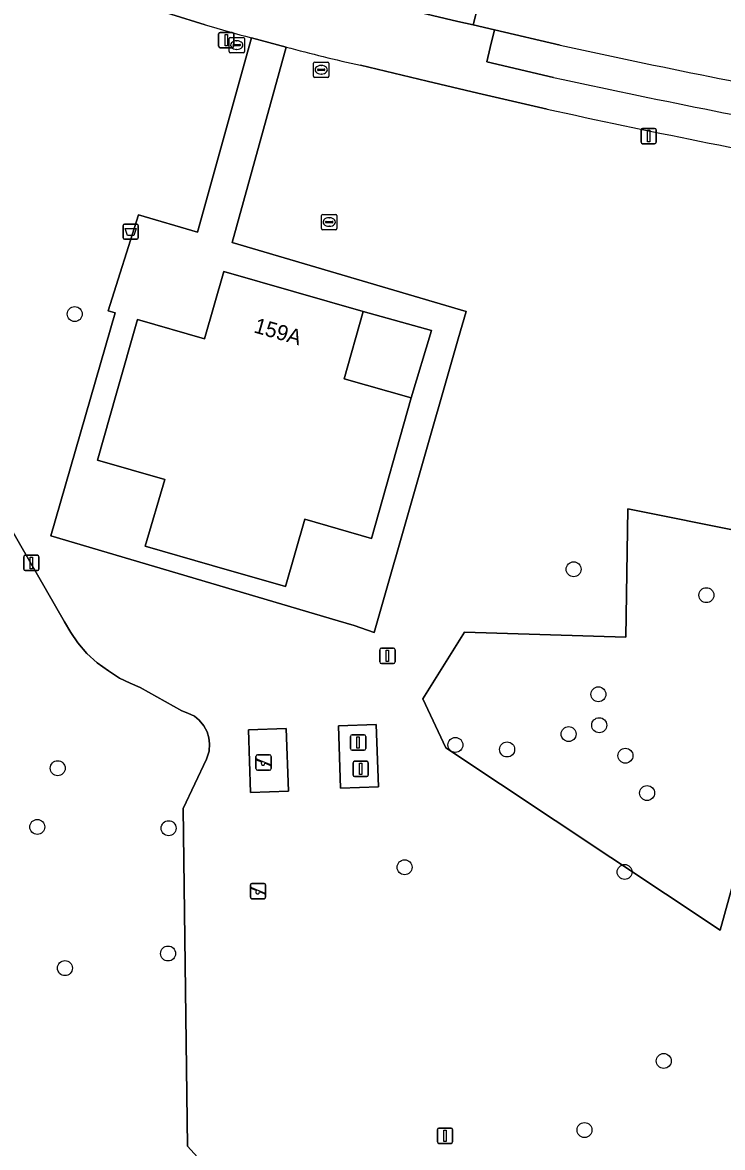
# Model space of a CAD drawing. Extents: x 161258 to 161838, y 380833 to 381727.
# Drawn here: x 161379.4 to 161425.2, y 381594 to 381667.5 of the extents above; entities that cross this region are included whole.
import ezdxf

# ---------------------------------------------------------------- set-up
doc = ezdxf.new("R2010")
doc.units = 0
for name, color, linetype in [('IMGEO_Afsluitpaal', 7, 'Continuous'), ('IMGEO_Afvalbak', 7, 'Continuous'), ('IMGEO_Boom', 7, 'Continuous'), ('IMGEO_Gemengd_bos', 7, 'Continuous'), ('IMGEO_Groenvoorziening', 7, 'Continuous'), ('IMGEO_Kolk', 7, 'Continuous'), ('IMGEO_Lichtmast', 7, 'Continuous'), ('IMGEO_Pand', 7, 'Continuous'), ('IMGEO_Pand_nummerreeks', 7, 'Continuous'), ('IMGEO_Parkeervlak_halfverhard', 7, 'Continuous'), ('IMGEO_Rijbaan_lokaal_open', 7, 'Continuous'), ('IMGEO_Rioolput', 7, 'Continuous'), ('IMGEO_Speelvoorziening', 7, 'Continuous'), ('IMGEO_Terreindeel_open', 7, 'Continuous'), ('IMGEO_Vlaggenmast', 7, 'Continuous'), ('IMGEO_Voetpad_open', 7, 'Continuous')]:
    doc.layers.add(name, color=color, linetype=linetype)

msp = doc.modelspace()

# ---------------------------------------------------------------- linework, layer by layer
at = {"layer": 'IMGEO_Afsluitpaal'}
for p, q in [((161400.856, 381620.042), (161400.856, 381620.842)), ((161400.856, 381620.842), (161400.856, 381620.042)), ((161400.956, 381620.942), (161401.746, 381620.942)), ((161401.746, 381620.942), (161400.956, 381620.942)), ((161401.846, 381620.842), (161401.846, 381620.042)), ((161401.846, 381620.042), (161401.846, 381620.842)), ((161401.746, 381619.942), (161400.956, 381619.942)), ((161400.956, 381619.942), (161401.746, 381619.942)), ((161401.023, 381618.318), (161401.023, 381619.118)), ((161401.023, 381619.118), (161401.023, 381618.318)), ((161401.123, 381619.218), (161401.913, 381619.218)), ((161401.913, 381619.218), (161401.123, 381619.218)), ((161402.013, 381619.118), (161402.013, 381618.318)), ((161402.013, 381618.318), (161402.013, 381619.118)), ((161401.913, 381618.218), (161401.123, 381618.218)), ((161401.123, 381618.218), (161401.913, 381618.218))]:
    msp.add_line(p, q, dxfattribs=at)
for points in [[(161401.276, 381620.817), (161401.426, 381620.817), (161401.426, 381620.067), (161401.276, 381620.067), (161401.276, 381620.817)], [(161401.443, 381619.093), (161401.593, 381619.093), (161401.593, 381618.343), (161401.443, 381618.343), (161401.443, 381619.093)]]:
    msp.add_lwpolyline(points, dxfattribs=at)
for centre, start, end in [((161400.956, 381620.842), 90, 180), ((161400.956, 381620.842), 90, 180), ((161401.746, 381620.842), 0, 90), ((161401.746, 381620.842), 360, 90), ((161400.956, 381620.042), 180, 270), ((161400.956, 381620.042), 180, 270), ((161401.746, 381620.042), 270, 0), ((161401.746, 381620.042), 270, 0), ((161401.123, 381619.118), 90, 180), ((161401.123, 381619.118), 90, 180), ((161401.913, 381619.118), 0, 90), ((161401.913, 381619.118), 360, 90), ((161401.123, 381618.318), 180, 270), ((161401.123, 381618.318), 180, 270), ((161401.913, 381618.318), 270, 0), ((161401.913, 381618.318), 270, 0)]:
    msp.add_arc(centre, 0.1, start, end, dxfattribs=at)
at = {"layer": 'IMGEO_Afvalbak'}
for p, q in [((161386.1, 381654.321), (161386.89, 381654.321)), ((161386.89, 381654.321), (161386.1, 381654.321)), ((161386, 381653.421), (161386, 381654.221)), ((161386, 381654.221), (161386, 381653.421)), ((161386.99, 381654.221), (161386.99, 381653.421)), ((161386.99, 381653.421), (161386.99, 381654.221)), ((161386.89, 381653.321), (161386.1, 381653.321)), ((161386.1, 381653.321), (161386.89, 381653.321))]:
    msp.add_line(p, q, dxfattribs=at)
msp.add_lwpolyline([(161386.143, 381654.035), (161386.847, 381654.035), (161386.698, 381653.565), (161386.292, 381653.565), (161386.143, 381654.035)], dxfattribs=at)
for centre, start, end in [((161386.1, 381654.221), 90, 180), ((161386.1, 381654.221), 90, 180), ((161386.89, 381654.221), 0, 90), ((161386.89, 381654.221), 360, 90), ((161386.1, 381653.421), 180, 270), ((161386.1, 381653.421), 180, 270), ((161386.89, 381653.421), 270, 0), ((161386.89, 381653.421), 270, 0)]:
    msp.add_arc(centre, 0.1, start, end, dxfattribs=at)
at = {"layer": 'IMGEO_Boom'}
for centre in [(161382.846, 381648.438), (161415.429, 381631.761), (161424.097, 381630.07), (161417.047, 381623.592), (161417.098, 381621.573), (161415.103, 381620.993), (161407.705, 381620.285), (161411.085, 381619.988), (161418.812, 381619.583), (161381.732, 381618.765), (161420.227, 381617.142), (161380.399, 381614.928), (161388.976, 381614.844), (161404.387, 381612.292), (161418.761, 381611.984), (161388.942, 381606.656), (161382.205, 381605.701), (161421.315, 381599.635), (161416.138, 381595.122)]:
    msp.add_circle(centre, 0.489, dxfattribs=at)
at = {"layer": 'IMGEO_Gemengd_bos'}
for points in [[(161392.773, 381591.226), (161390.219, 381594.066), (161389.922, 381616.123), (161391.46, 381619.355), (161391.634, 381619.875), (161391.656, 381620.356), (161391.605, 381620.751), (161391.491, 381621.146), (161391.275, 381621.526), (161390.981, 381621.893), (161390.658, 381622.158), (161390.242, 381622.367), (161389.838, 381622.503), (161387.123, 381624.033), (161386.473, 381624.327), (161385.77, 381624.643), (161385.052, 381625.131), (161384.32, 381625.648), (161383.645, 381626.251), (161383.057, 381626.955), (161382.583, 381627.63), (161382.181, 381628.334), (161376.186, 381638.709)], [(161426.68, 381634.173), (161418.967, 381635.706), (161418.846, 381627.333), (161408.294, 381627.656), (161405.585, 381623.296), (161407.091, 381620.098), (161424.991, 381608.183), (161426.307, 381612.909)]]:
    msp.add_lwpolyline(points, dxfattribs=at)
at = {"layer": 'IMGEO_Groenvoorziening'}
for points in [[(161391.37, 381667.33), (161386.886, 381668.72), (161334.877, 381686.353), (161332.875, 381684.207), (161332.497, 381684.358), (161308.899, 381657.34), (161323.248, 381645.463), (161342.599, 381633.765), (161351.063, 381627.808), (161358.392, 381621.525), (161365.093, 381614.244), (161367.696, 381609.218), (161369.804, 381602.566), (161370.364, 381589.068), (161368.045, 381579.46), (161365.828, 381572.142), (161359.235, 381542.5), (161358.088, 381525.588)], [(161381.277, 381633.951), (161385.48, 381648.52), (161385.02, 381648.657), (161387, 381654.92), (161390.867, 381653.781), (161394.382, 381666.485)], [(161396.659, 381665.882), (161393.126, 381653.115), (161408.406, 381648.613), (161407.893, 381646.823), (161402.4, 381627.633), (161401.084, 381628.097), (161400.041, 381628.391), (161381.277, 381633.951)], [(161413.689, 381661.83), (161409.167, 381662.867), (161405.857, 381663.645), (161401.512, 381664.693)], [(161376.186, 381638.709), (161382.181, 381628.334), (161382.583, 381627.63), (161383.057, 381626.955), (161383.645, 381626.251), (161384.32, 381625.648), (161385.052, 381625.131), (161385.77, 381624.643), (161386.473, 381624.327), (161387.123, 381624.033), (161389.838, 381622.503), (161390.242, 381622.367), (161390.658, 381622.158), (161390.981, 381621.893), (161391.275, 381621.526), (161391.491, 381621.146), (161391.605, 381620.751), (161391.656, 381620.356), (161391.634, 381619.875), (161391.46, 381619.355), (161389.922, 381616.123), (161390.219, 381594.066), (161392.773, 381591.226)], [(161451.968, 381587.039), (161454.812, 381586.172), (161454.469, 381587.787), (161449.116, 381608.641), (161435.423, 381611.203), (161433.603, 381611.544), (161428.272, 381612.541), (161426.307, 381612.909), (161424.991, 381608.183), (161407.091, 381620.098), (161405.585, 381623.296), (161408.294, 381627.656), (161418.846, 381627.333), (161418.967, 381635.706), (161426.68, 381634.173), (161443.415, 381630.846), (161443.337, 381631.151)]]:
    msp.add_lwpolyline(points, dxfattribs=at)
for points in [[(161396.654, 381621.359), (161396.798, 381617.269), (161394.33, 381617.182), (161394.185, 381621.271)], [(161402.53, 381621.627), (161402.675, 381617.537), (161400.206, 381617.45), (161400.062, 381621.539)]]:
    msp.add_lwpolyline(points, close=True, dxfattribs=at)
for centre, radius, start, end in [((161433.329, 381811.102), 149.77, 253.73044, 254.92722), ((161423.506, 381764.962), 102.653, 254.83898, 257.62808), ((161532.028, 382200.983), 551.988, 257.62047, 259.73428)]:
    msp.add_arc(centre, radius, start, end, dxfattribs=at)
at = {"layer": 'IMGEO_Kolk'}
for p, q in [((161392.928, 381665.587), (161392.928, 381666.439)), ((161393.003, 381666.513), (161393.855, 381666.513)), ((161393.187, 381666.007), (161393.187, 381666.019)), ((161393.23, 381666.056), (161393.628, 381666.056)), ((161393.416, 381666.293), (161393.441, 381666.293)), ((161393.671, 381666.019), (161393.671, 381666.007)), ((161393.929, 381666.439), (161393.929, 381665.587)), ((161393.855, 381665.513), (161393.003, 381665.513)), ((161393.625, 381665.97), (161393.227, 381665.97)), ((161393.439, 381665.733), (161393.414, 381665.733)), ((161398.443, 381663.974), (161398.443, 381664.826)), ((161398.518, 381664.9), (161399.37, 381664.9)), ((161398.931, 381664.68), (161398.956, 381664.68)), ((161399.444, 381664.826), (161399.444, 381663.974)), ((161399.37, 381663.9), (161398.518, 381663.9)), ((161398.702, 381664.394), (161398.702, 381664.406)), ((161399.14, 381664.357), (161398.742, 381664.357)), ((161398.745, 381664.443), (161399.143, 381664.443)), ((161398.954, 381664.12), (161398.929, 381664.12)), ((161399.186, 381664.406), (161399.186, 381664.394))]:
    msp.add_line(p, q, dxfattribs=at)
for points in [[(161392.928, 381665.587), (161392.928, 381666.439)], [(161393.003, 381666.513), (161393.855, 381666.513)], [(161393.929, 381666.439), (161393.929, 381665.587)], [(161393.855, 381665.513), (161393.003, 381665.513)], [(161398.443, 381663.974), (161398.443, 381664.826)], [(161398.518, 381664.9), (161399.37, 381664.9)], [(161399.444, 381664.826), (161399.444, 381663.974)], [(161399.37, 381663.9), (161398.518, 381663.9)]]:
    msp.add_lwpolyline(points, dxfattribs=at)
for centre, radius, start, end in [((161393.005, 381666.437), 0.0765, 91.55205, 178.44795), ((161393.005, 381666.437), 0.0765, 91.55205, 178.44795), ((161393.227, 381666.016), 0.0403, 85.87752, 175.75265), ((161393.224, 381666.006), 0.0366, 178.93798, 274.71019), ((161393.628, 381666.013), 0.043, 264.86636, 352.45326), ((161393.632, 381666.018), 0.0386, 1.73085, 96.63898), ((161393.853, 381666.437), 0.0765, 1.55205, 88.44795), ((161393.853, 381666.437), 0.0765, 1.55205, 88.44795), ((161393.005, 381665.589), 0.0765, 181.55205, 268.44795), ((161393.005, 381665.589), 0.0765, 181.55205, 268.44795), ((161393.853, 381665.589), 0.0765, 271.55205, 358.44795), ((161393.853, 381665.589), 0.0765, 271.55205, 358.44795), ((161398.52, 381664.824), 0.0765, 91.55205, 178.44795), ((161398.52, 381664.824), 0.0765, 91.55205, 178.44795), ((161399.368, 381664.824), 0.0765, 1.55205, 88.44795), ((161399.368, 381664.824), 0.0765, 1.55205, 88.44795), ((161398.52, 381663.976), 0.0765, 181.55205, 268.44795), ((161398.52, 381663.976), 0.0765, 181.55205, 268.44795), ((161398.742, 381664.403), 0.0403, 85.87752, 175.75265), ((161398.739, 381664.393), 0.0366, 178.93798, 274.71019), ((161399.143, 381664.4), 0.043, 264.86636, 352.45326), ((161399.147, 381664.405), 0.0386, 1.73085, 96.63898), ((161399.368, 381663.976), 0.0765, 271.55205, 358.44795), ((161399.368, 381663.976), 0.0765, 271.55205, 358.44795)]:
    msp.add_arc(centre, radius, start, end, dxfattribs=at)
for centre, major_axis, ratio, start_param, end_param in [((161393.415, 381666.013), (-0.387, 0.002), 0.722429, 4.712389, 7.853982), ((161393.44, 381666.013), (-0.39, 0.002), 0.717154, 1.570796, 4.712389), ((161398.93, 381664.4), (-0.387, 0.002), 0.722429, 4.712389, 7.853982), ((161398.955, 381664.4), (-0.39, 0.002), 0.717154, 1.570796, 4.712389)]:
    msp.add_ellipse(centre, major_axis=major_axis, ratio=ratio, start_param=start_param, end_param=end_param, dxfattribs=at)
at = {"layer": 'IMGEO_Lichtmast'}
for p, q in [((161392.241, 381665.938), (161392.241, 381666.738)), ((161392.241, 381666.738), (161392.241, 381665.938)), ((161392.341, 381666.838), (161393.131, 381666.838)), ((161393.131, 381666.838), (161392.341, 381666.838)), ((161393.231, 381666.738), (161393.231, 381665.938)), ((161393.231, 381665.938), (161393.231, 381666.738)), ((161393.131, 381665.838), (161392.341, 381665.838)), ((161392.341, 381665.838), (161393.131, 381665.838)), ((161419.83, 381659.668), (161419.83, 381660.468)), ((161419.83, 381660.468), (161419.83, 381659.668)), ((161419.93, 381660.568), (161420.72, 381660.568)), ((161420.72, 381660.568), (161419.93, 381660.568)), ((161420.82, 381660.468), (161420.82, 381659.668)), ((161420.82, 381659.668), (161420.82, 381660.468)), ((161420.72, 381659.568), (161419.93, 381659.568)), ((161419.93, 381659.568), (161420.72, 381659.568)), ((161379.514, 381631.774), (161379.514, 381632.574)), ((161379.514, 381632.574), (161379.514, 381631.774)), ((161379.614, 381632.674), (161380.404, 381632.674)), ((161380.404, 381632.674), (161379.614, 381632.674)), ((161380.504, 381632.574), (161380.504, 381631.774)), ((161380.504, 381631.774), (161380.504, 381632.574)), ((161380.404, 381631.674), (161379.614, 381631.674)), ((161379.614, 381631.674), (161380.404, 381631.674)), ((161402.774, 381625.708), (161402.774, 381626.508)), ((161402.774, 381626.508), (161402.774, 381625.708)), ((161402.874, 381626.608), (161403.664, 381626.608)), ((161403.664, 381626.608), (161402.874, 381626.608)), ((161403.764, 381626.508), (161403.764, 381625.708)), ((161403.764, 381625.708), (161403.764, 381626.508)), ((161403.664, 381625.608), (161402.874, 381625.608)), ((161402.874, 381625.608), (161403.664, 381625.608))]:
    msp.add_line(p, q, dxfattribs=at)
for points in [[(161392.661, 381666.713), (161392.811, 381666.713), (161392.811, 381665.963), (161392.661, 381665.963), (161392.661, 381666.713)], [(161420.25, 381660.443), (161420.4, 381660.443), (161420.4, 381659.693), (161420.25, 381659.693), (161420.25, 381660.443)], [(161379.934, 381632.549), (161380.084, 381632.549), (161380.084, 381631.799), (161379.934, 381631.799), (161379.934, 381632.549)], [(161403.194, 381626.483), (161403.344, 381626.483), (161403.344, 381625.733), (161403.194, 381625.733), (161403.194, 381626.483)]]:
    msp.add_lwpolyline(points, dxfattribs=at)
for centre, start, end in [((161392.341, 381666.738), 90, 180), ((161392.341, 381666.738), 90, 180), ((161393.131, 381666.738), 0, 90), ((161393.131, 381666.738), 360, 90), ((161392.341, 381665.938), 180, 270), ((161392.341, 381665.938), 180, 270), ((161393.131, 381665.938), 270, 0), ((161393.131, 381665.938), 270, 0), ((161419.93, 381660.468), 90, 180), ((161419.93, 381660.468), 90, 180), ((161420.72, 381660.468), 0, 90), ((161420.72, 381660.468), 360, 90), ((161419.93, 381659.668), 180, 270), ((161419.93, 381659.668), 180, 270), ((161420.72, 381659.668), 270, 0), ((161420.72, 381659.668), 270, 0), ((161379.614, 381632.574), 90, 180), ((161379.614, 381632.574), 90, 180), ((161380.404, 381632.574), 0, 90), ((161380.404, 381632.574), 360, 90), ((161379.614, 381631.774), 180, 270), ((161379.614, 381631.774), 180, 270), ((161380.404, 381631.774), 270, 0), ((161380.404, 381631.774), 270, 0), ((161402.874, 381626.508), 90, 180), ((161402.874, 381626.508), 90, 180), ((161403.664, 381626.508), 0, 90), ((161403.664, 381626.508), 360, 90), ((161402.874, 381625.708), 180, 270), ((161402.874, 381625.708), 180, 270), ((161403.664, 381625.708), 270, 0), ((161403.664, 381625.708), 270, 0)]:
    msp.add_arc(centre, 0.1, start, end, dxfattribs=at)
at = {"layer": 'IMGEO_Pand'}
msp.add_lwpolyline([(161391.811, 381632.008), (161396.616, 381630.626), (161397.868, 381635.027), (161402.225, 381633.783), (161404.821, 381642.967), (161400.446, 381644.203), (161401.691, 381648.594), (161392.583, 381651.21), (161391.312, 381646.822), (161386.934, 381648.077), (161385.571, 381643.267), (161384.329, 381638.884), (161388.72, 381637.631), (161387.454, 381633.261)], close=True, dxfattribs=at)
at = {"layer": 'IMGEO_Parkeervlak_halfverhard'}
for points in [[(161410.252, 381667.011), (161409.976, 381665.854), (161409.753, 381664.915), (161414.118, 381663.89)], [(161414.539, 381666.017), (161410.252, 381667.011)]]:
    msp.add_lwpolyline(points, dxfattribs=at)
for centre, radius, start, end in [((161527.118, 382176.509), 522.758, 257.56362, 259.75352), ((161554.462, 382315.521), 666.573, 257.845672, 259.579042)]:
    msp.add_arc(centre, radius, start, end, dxfattribs=at)
at = {"layer": 'IMGEO_Rijbaan_lokaal_open'}
for points in [[(161391.451, 381676.967), (161389.444, 381677.652), (161387.854, 381672.902), (161388.263, 381672.768), (161390.477, 381672.041), (161394.352, 381670.897), (161397.402, 381670.053), (161407.867, 381667.561), (161408.872, 381667.329), (161409.853, 381671.143), (161407.873, 381671.648)], [(161409.853, 381671.143), (161408.872, 381667.329), (161410.252, 381667.011), (161414.539, 381666.017)]]:
    msp.add_lwpolyline(points, dxfattribs=at)
msp.add_arc((161527.118, 382176.509), 522.758, 257.56362, 259.75352, dxfattribs=at)
at = {"layer": 'IMGEO_Rioolput'}
for p, q in [((161398.968, 381654.025), (161398.968, 381654.877)), ((161399.043, 381654.951), (161399.895, 381654.951)), ((161399.227, 381654.445), (161399.227, 381654.457)), ((161399.665, 381654.408), (161399.267, 381654.408)), ((161399.27, 381654.494), (161399.668, 381654.494)), ((161399.456, 381654.731), (161399.481, 381654.731)), ((161399.711, 381654.457), (161399.711, 381654.445)), ((161399.969, 381654.877), (161399.969, 381654.025)), ((161399.895, 381653.951), (161399.043, 381653.951)), ((161399.479, 381654.171), (161399.454, 381654.171))]:
    msp.add_line(p, q, dxfattribs=at)
for points in [[(161398.968, 381654.025), (161398.968, 381654.877)], [(161399.043, 381654.951), (161399.895, 381654.951)], [(161399.969, 381654.877), (161399.969, 381654.025)], [(161399.895, 381653.951), (161399.043, 381653.951)]]:
    msp.add_lwpolyline(points, dxfattribs=at)
for centre, radius, start, end in [((161399.045, 381654.875), 0.0765, 91.55205, 178.44795), ((161399.045, 381654.875), 0.0765, 91.55205, 178.44795), ((161399.267, 381654.454), 0.0403, 85.87752, 175.75265), ((161399.264, 381654.444), 0.0366, 178.93798, 274.71019), ((161399.668, 381654.451), 0.043, 264.86636, 352.45326), ((161399.672, 381654.456), 0.0386, 1.73085, 96.63898), ((161399.893, 381654.875), 0.0765, 1.55205, 88.44795), ((161399.893, 381654.875), 0.0765, 1.55205, 88.44795), ((161399.045, 381654.027), 0.0765, 181.55205, 268.44795), ((161399.045, 381654.027), 0.0765, 181.55205, 268.44795), ((161399.893, 381654.027), 0.0765, 271.55205, 358.44795), ((161399.893, 381654.027), 0.0765, 271.55205, 358.44795)]:
    msp.add_arc(centre, radius, start, end, dxfattribs=at)
for centre, major_axis, ratio, start_param, end_param in [((161399.455, 381654.451), (-0.387, 0.002), 0.722429, 4.712389, 7.853982), ((161399.48, 381654.451), (-0.39, 0.002), 0.717154, 1.570796, 4.712389)]:
    msp.add_ellipse(centre, major_axis=major_axis, ratio=ratio, start_param=start_param, end_param=end_param, dxfattribs=at)
at = {"layer": 'IMGEO_Speelvoorziening'}
for p, q in [((161394.682, 381618.735), (161394.682, 381619.535)), ((161394.682, 381619.535), (161394.682, 381618.735)), ((161395.065, 381619.163), (161394.726, 381619.3)), ((161394.751, 381619.36), (161395.627, 381619.007)), ((161394.782, 381619.635), (161395.572, 381619.635)), ((161395.572, 381619.635), (161394.782, 381619.635)), ((161395.603, 381618.947), (161395.263, 381619.084)), ((161395.672, 381619.535), (161395.672, 381618.735)), ((161395.672, 381618.735), (161395.672, 381619.535)), ((161395.572, 381618.635), (161394.782, 381618.635)), ((161394.782, 381618.635), (161395.572, 381618.635)), ((161394.321, 381610.337), (161394.321, 381611.137)), ((161394.321, 381611.137), (161394.321, 381610.337)), ((161394.704, 381610.765), (161394.365, 381610.902)), ((161394.39, 381610.962), (161395.266, 381610.609)), ((161394.421, 381611.237), (161395.211, 381611.237)), ((161395.211, 381611.237), (161394.421, 381611.237)), ((161395.311, 381611.137), (161395.311, 381610.337)), ((161395.311, 381610.337), (161395.311, 381611.137)), ((161395.211, 381610.237), (161394.421, 381610.237)), ((161394.421, 381610.237), (161395.211, 381610.237)), ((161395.242, 381610.549), (161394.902, 381610.686))]:
    msp.add_line(p, q, dxfattribs=at)
for centre, radius, start, end in [((161394.782, 381619.535), 0.1, 90, 180), ((161394.782, 381619.535), 0.1, 90, 180), ((161394.739, 381619.33), 0.0327, 68.07798, 248.07798), ((161395.144, 381619.073), 0.12, 130.99278, 5.16318), ((161395.572, 381619.535), 0.1, 0, 90), ((161395.572, 381619.535), 0.1, 360, 90), ((161395.615, 381618.977), 0.0327, 248.07798, 68.07798), ((161394.782, 381618.735), 0.1, 180, 270), ((161394.782, 381618.735), 0.1, 180, 270), ((161395.572, 381618.735), 0.1, 270, 0), ((161395.572, 381618.735), 0.1, 270, 0), ((161394.421, 381611.137), 0.1, 90, 180), ((161394.421, 381611.137), 0.1, 90, 180), ((161394.378, 381610.932), 0.0327, 68.07798, 248.07798), ((161395.211, 381611.137), 0.1, 0, 90), ((161395.211, 381611.137), 0.1, 360, 90), ((161394.421, 381610.337), 0.1, 180, 270), ((161394.421, 381610.337), 0.1, 180, 270), ((161394.783, 381610.675), 0.12, 130.99278, 5.16318), ((161395.211, 381610.337), 0.1, 270, 0), ((161395.211, 381610.337), 0.1, 270, 0), ((161395.254, 381610.579), 0.0327, 248.07798, 68.07798)]:
    msp.add_arc(centre, radius, start, end, dxfattribs=at)
at = {"layer": 'IMGEO_Terreindeel_open'}
for points in [[(161404.821, 381642.967), (161406.142, 381647.362), (161401.691, 381648.594), (161400.446, 381644.203)], [(161396.654, 381621.359), (161394.185, 381621.271), (161394.33, 381617.182), (161396.798, 381617.269)], [(161402.53, 381621.627), (161400.062, 381621.539), (161400.206, 381617.45), (161402.675, 381617.537)]]:
    msp.add_lwpolyline(points, close=True, dxfattribs=at)
at = {"layer": 'IMGEO_Vlaggenmast'}
for p, q in [((161406.529, 381594.347), (161406.529, 381595.147)), ((161406.529, 381595.147), (161406.529, 381594.347)), ((161406.629, 381595.247), (161407.419, 381595.247)), ((161407.419, 381595.247), (161406.629, 381595.247)), ((161407.519, 381595.147), (161407.519, 381594.347)), ((161407.519, 381594.347), (161407.519, 381595.147)), ((161407.419, 381594.247), (161406.629, 381594.247)), ((161406.629, 381594.247), (161407.419, 381594.247))]:
    msp.add_line(p, q, dxfattribs=at)
msp.add_lwpolyline([(161406.949, 381595.122), (161407.099, 381595.122), (161407.099, 381594.372), (161406.949, 381594.372), (161406.949, 381595.122)], dxfattribs=at)
for centre, start, end in [((161406.629, 381595.147), 90, 180), ((161406.629, 381595.147), 90, 180), ((161407.419, 381595.147), 0, 90), ((161407.419, 381595.147), 360, 90), ((161406.629, 381594.347), 180, 270), ((161406.629, 381594.347), 180, 270), ((161407.419, 381594.347), 270, 0), ((161407.419, 381594.347), 270, 0)]:
    msp.add_arc(centre, 0.1, start, end, dxfattribs=at)
at = {"layer": 'IMGEO_Voetpad_open'}
for points in [[(161409.753, 381664.915), (161409.976, 381665.854), (161410.252, 381667.011), (161408.872, 381667.329), (161407.867, 381667.561), (161397.402, 381670.053), (161394.352, 381670.897), (161390.477, 381672.041), (161388.263, 381672.768), (161387.916, 381671.748), (161387.563, 381670.711), (161386.954, 381668.921), (161386.886, 381668.72), (161391.37, 381667.33)], [(161394.382, 381666.485), (161396.659, 381665.882)], [(161401.512, 381664.693), (161405.857, 381663.645), (161409.167, 381662.867), (161413.689, 381661.83)], [(161414.118, 381663.89), (161409.753, 381664.915)]]:
    msp.add_lwpolyline(points, dxfattribs=at)
for points in [[(161396.659, 381665.882), (161394.382, 381666.485), (161390.867, 381653.781), (161387, 381654.92), (161385.02, 381648.657), (161385.48, 381648.52), (161381.277, 381633.951), (161400.041, 381628.391), (161401.084, 381628.097), (161402.4, 381627.633), (161407.893, 381646.823), (161408.406, 381648.613), (161393.126, 381653.115)], [(161401.691, 381648.594), (161406.142, 381647.362), (161404.821, 381642.967), (161402.225, 381633.783), (161397.868, 381635.027), (161396.616, 381630.626), (161391.811, 381632.008), (161387.454, 381633.261), (161388.72, 381637.631), (161384.329, 381638.884), (161385.571, 381643.267), (161386.934, 381648.077), (161391.312, 381646.822), (161392.583, 381651.21)]]:
    msp.add_lwpolyline(points, close=True, dxfattribs=at)
for centre, radius, start, end in [((161433.329, 381811.102), 149.77, 253.73044, 254.92722), ((161423.506, 381764.962), 102.653, 254.83898, 257.62808), ((161554.462, 382315.521), 666.573, 257.845672, 259.579042), ((161532.028, 382200.983), 551.988, 257.62047, 259.73428)]:
    msp.add_arc(centre, radius, start, end, dxfattribs=at)

# ---------------------------------------------------------------- texts
at = {"layer": 'IMGEO_Pand_nummerreeks'}
msp.add_text('159A', height=1, rotation=343.97487, dxfattribs=at).set_placement((161394.484, 381647.251))

doc.saveas('drawing.dxf')
